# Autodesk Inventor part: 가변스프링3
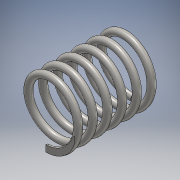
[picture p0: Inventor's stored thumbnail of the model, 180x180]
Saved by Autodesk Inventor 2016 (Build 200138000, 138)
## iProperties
Created: 2021-02
Part Number: 가변스프링3
Material: 강철, 탄소
Document SubType Name: Modeling
Designer: Windows7
Density: 7.85 g/cm^3
Appearance: 반연마
Mass: 7.77533 g
Surface Area: 20.0935 cm^2
Volume: 0.990488 cm^3
Author: Windows7
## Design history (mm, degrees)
sketch "스케치1"
  geometry: L1 (0, 0)-(26.33, 0); L2 (26.33, 0)-(26.33, -8.5); L3 (26.33, -8.5)-(0, -8.5); L4 (0, -8.5)-(0, 0); C1 r 1 at (26.33, -8.5)
  constraints: 8 end point, 2 parallel, 1 centre point, 1 coincident, 1 horizontal, 1 perpendicular
  dimensions: "d0" = 26.33013 distance between parallel lines of L4 L2 (derived); "d1" = 17 diameter of L3 L1; "d2" = 2 diameter of C1
feature "코일1" sketch "스케치1" pitch "d3" = 10; turns "d5" = 6; dims "d4" = 26.33013 (= d0), "d6" = 0, angle "d7" = 90 deg, angle "d8" = 90 deg, "d9" = 0, "d10" = 0
sketch "스케치2"
  geometry: L1 (0, -7.5)-(0, -9.5) reference; 1 further point
  constraints: 1 vertical alignment
extrude "돌출1" cut sketch "스케치2" distance "d11" = 10; taper "d12" = 0 deg
node "작업 평면1"
sketch "스케치3"
  geometry: L1 (7.5, 0)-(9.5, 0) reference; 2 further points
  constraints: 2 other
extrude "돌출2" cut sketch "스케치3" distance "d14" = 10; taper "d15" = 0 deg
node "솔리드1"
node "절단 모서리 투영1"
node "절단 모서리 투영2"
other parameters: "d13" = 90 deg
